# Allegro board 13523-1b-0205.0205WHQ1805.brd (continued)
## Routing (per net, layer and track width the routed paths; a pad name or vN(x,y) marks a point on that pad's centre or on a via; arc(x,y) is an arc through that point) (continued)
PCIE_SLOT0_RXN5: length 59.1
  BOTTOM w0.165: CN1.A26 54.79,55.83 54.86,55.61 55.1,55.49 55.28,55.08 55.28,52.44 55.28,52.44 55.28,52.05 55.28,51.85 55.57,51.3 56.06,50.95 56.29,50.49 56.43,49.14 56.88,47.07 56.79,46.55 54.06,31.07 38.58,8.97 38.29,7.32 38.29,6.11 38.65,5.75 GF1.A26
PCIE_SLOT0_RXN6: length 58.9
  BOTTOM w0.165: GF1.A22 34.65,5.74 34.29,6.1 34.29,8.31 34.49,9.44 49.39,30.72 52.5,48.38 52.29,50.49 52.06,50.95 51.57,51.3 51.28,51.85 51.28,52.05 51.28,52.44 51.32,54.68 51.12,55.48 50.86,55.61 50.79,55.83 CN1.A22
PCIE_SLOT0_RXN7: length 60.7
  BOTTOM w0.165: GF1.A17 29.65,5.75 29.29,6.11 29.29,8.02 29.38,8.55 29.69,8.99 31.34,10.15 45.8,30.79 47.81,42.19 47.94,42.28 48.02,42.76 47.93,42.89 48.02,43.38 48.15,43.47 48.23,43.96 48.14,44.09 48.23,44.58 48.36,44.67 48.44,45.16 48.35,45.29 48.44,45.77 48.5,46.12 48.52,46.25 48.23,48.29 48.31,50.08 48.27,50.61 47.96,50.99 47.61,51.24 47.33,51.54 47.3,52.31 47.1,52.79 46.71,53.12 45.98,53.28 45.37,54.01 45.3,54.66 45.42,55.29 45.56,55.36 45.79,55.29 CN1.A17
PCIE_SLOT0_RXP0: length 58
  BOTTOM w0.165: CN1.A47 76.51,55.29 76.74,55.36 76.88,55.29 77.01,54.61 77,52.08 76.86,51.4 76.41,51 76.08,50.58 76.04,50.06 76.04,49.56 75.93,49.45 75.94,48.95 76.05,48.84 76.06,48.35 75.95,48.23 75.95,47.74 76.07,47.63 76.07,47.13 75.96,47.02 75.97,46.52 76.08,46.41 76.09,45.6 73.79,32.52 61.55,15.05 60.01,6.3 60.01,6.11 59.65,5.75 GF1.A47
PCIE_SLOT0_RXP1: length 59
  BOTTOM w0.165: GF1.A43 55.65,5.75 56.01,6.11 56.01,6.99 56.74,11.12 72.2,33.2 74.46,46.01 74.38,46.79 74.26,46.89 74.21,47.38 74.31,47.5 74.26,48 74.14,48.1 74.09,48.59 74.19,48.71 74.14,49.2 74.02,49.3 73.97,49.8 74.07,49.92 74.02,50.41 73.84,50.76 73.35,51.11 73.03,51.72 73,51.78 73,51.89 73,52.57 73.01,54.61 72.88,55.29 72.74,55.36 72.61,55.32 72.45,55.17 CN1.A43
PCIE_SLOT0_RXP2: length 59
  BOTTOM w0.165: CN1.A39 68.51,55.29 68.74,55.36 68.88,55.29 68.88,55.29 69.01,54.85 69,52.44 69,52.05 69,51.78 69.35,51.11 69.84,50.76 70.02,50.41 70.06,49.98 70.09,49.72 70.13,49.25 70.15,49.1 70.63,47.11 70.52,46.46 70.43,45.97 70.3,45.88 70.22,45.39 70.31,45.26 70.22,44.78 70.09,44.68 70.01,44.2 70.1,44.07 70.01,43.58 69.88,43.49 69.8,43 69.89,42.87 67.77,30.88 52.31,8.8 52.01,7.11 52.01,6.11 51.65,5.75 GF1.A39
PCIE_SLOT0_RXP3: length 58.9
  BOTTOM w0.165: GF1.A35 47.65,5.75 48.01,6.11 48.01,7.77 48.09,8.25 63.12,29.71 65.66,44.1 65.57,44.23 65.65,44.72 65.78,44.81 65.87,45.3 65.78,45.43 65.87,45.91 65.99,46.01 66.08,46.49 65.99,46.62 66.08,47.11 66.21,47.2 66.29,47.69 66.02,50.4 66.02,50.41 65.84,50.76 65.35,51.11 65,51.78 65,52.05 65,52.44 65,52.45 65.04,54.68 64.88,55.29 64.74,55.36 64.51,55.29 CN1.A35
PCIE_SLOT0_RXP4: length 58.7
  BOTTOM w0.165: GF1.A29 41.65,5.75 42.01,6.11 42.01,7.55 42.36,9.52 56.81,30.16 59.52,45.51 59.43,45.64 59.51,46.13 59.64,46.22 59.73,46.71 59.64,46.83 59.72,47.32 59.85,47.41 59.94,47.9 59.85,48.03 59.94,48.52 60.06,48.61 60.15,49.1 60.02,50.41 59.84,50.76 59.35,51.11 59,51.78 59,52.05 59,52.44 59.04,54.59 58.88,55.29 58.74,55.36 58.51,55.29 CN1.A29
PCIE_SLOT0_RXP5: length 59
  BOTTOM w0.165: CN1.A25 54.51,55.29 54.74,55.36 54.88,55.29 55,55.02 55,52.44 55,52.05 55,51.78 55.35,51.11 55.84,50.76 56.02,50.41 56.15,49.09 56.59,47.06 56.51,46.6 56.43,46.11 56.3,46.02 56.21,45.54 56.3,45.41 56.22,44.92 56.09,44.83 56,44.34 56.09,44.21 56.01,43.72 55.88,43.63 55.79,43.14 55.88,43.01 53.79,31.18 38.31,9.07 38.01,7.35 38.01,6.11 37.65,5.75 GF1.A25
PCIE_SLOT0_RXP6: length 58.8
  BOTTOM w0.165: CN1.A21 50.51,55.29 50.74,55.36 50.88,55.29 51.04,54.65 51,52.46 51,52.44 51,52.05 51,51.78 51.35,51.11 51.84,50.76 51.97,50.51 52.02,50.41 52.22,48.39 52.13,47.91 52.01,47.82 51.92,47.33 52.01,47.2 51.92,46.71 51.79,46.62 51.71,46.13 51.8,46 51.71,45.51 51.58,45.42 51.5,44.94 51.59,44.81 49.12,30.83 34.22,9.55 34.01,8.34 34.01,6.12 33.65,5.76 GF1.A21
PCIE_SLOT0_RXP7: length 60.7
  BOTTOM w0.165: CN1.A16 45.51,55.83 45.44,55.61 45.17,55.47 45.02,54.67 45.1,53.89 45.82,53.02 46.58,52.86 46.87,52.62 47.02,52.25 47.06,51.43 47.42,51.03 47.77,50.78 47.99,50.5 48.03,50.08 47.95,48.27 48.24,46.25 48.16,45.82 45.53,30.9 31.14,10.35 29.49,9.19 29.12,8.66 29.01,8.05 29.01,6.11 28.65,5.75 GF1.A16
PCIE_SLOT0_TXN0: length 53.1
  TOP w0.165: GF1.B46 58.65,5.75 58.29,6.11 58.29,8 58.51,9.27 58.64,9.37 58.73,9.85 58.64,9.98 58.73,10.47 58.86,10.56 58.94,11.05 58.85,11.18 58.94,11.67 59.07,11.76 59.15,12.24 59.06,12.37 61.23,24.66 61.67,27.19 74.4,45.36 74.4,45.37 74.4,45.37 74.46,45.52 74.47,45.53 74.69,46.4 74.7,46.42 74.77,47.3 74.3,50.03 74.25,50.37 74.27,50.61 74.42,50.79 74.56,50.86 74.79,50.79 CN1.B46
PCIE_SLOT0_TXN1: length 53
  TOP w0.165: CN1.B42 70.79,50.79 70.57,50.86 70.42,50.79 70.27,50.61 70.25,50.37 70.3,50.03 70.4,49.45 70.58,48.39 70.74,47.35 70.73,47.3 70.44,46.36 69.38,43.88 69.36,43.86 57.68,27.17 54.95,11.73 55.05,11.6 54.96,11.11 54.83,11.02 54.74,10.53 54.83,10.4 54.75,9.91 54.62,9.82 54.53,9.34 54.62,9.21 54.54,8.72 54.41,8.63 54.29,7.96 54.29,6.11 54.65,5.75 GF1.B42
PCIE_SLOT0_TXN2: length 52.9
  TOP w0.165: CN1.B38 66.79,50.79 66.57,50.86 66.42,50.79 66.27,50.61 66.25,50.37 66.3,50.03 66.76,47.33 66.28,44.38 53.06,23.56 50.96,11.62 51.05,11.49 50.96,11 50.83,10.91 50.75,10.42 50.84,10.29 50.75,9.81 50.62,9.72 50.53,9.23 50.63,9.1 50.54,8.61 50.41,8.52 50.29,7.84 50.29,6.11 50.65,5.75 GF1.B38
PCIE_SLOT0_TXN3: length 53.3
  TOP w0.165: CN1.B34 62.79,50.79 62.56,50.86 62.42,50.79 62.27,50.61 62.24,50.37 62.3,50.03 62.66,47.9 62.76,47.34 62.26,44.49 62.2,44.17 62.15,43.87 61.39,39.57 48.19,20.71 46.68,12.2 46.78,12.07 46.69,11.58 46.56,11.49 46.47,11 46.56,10.87 46.48,10.39 46.35,10.29 46.26,9.81 46.35,9.68 46.27,9.19 46.14,9.1 45.99,8.26 46.29,6.56 46.29,6.11 46.65,5.75 GF1.B34
PCIE_SLOT0_TXN4: length 53.1
  TOP w0.165: CN1.B28 56.79,50.79 56.57,50.86 56.42,50.79 56.27,50.61 56.25,50.37 56.3,50.03 56.61,48.21 56.62,48.19 56.62,46.85 56.62,45.58 56.59,45.3 56.59,45.29 54.58,33.91 41.78,15.62 41.14,11.99 41.23,11.86 41.14,11.37 41.01,11.28 40.92,10.79 41.01,10.66 40.93,10.17 40.8,10.08 40.71,9.59 40.8,9.47 40.72,8.98 40.59,8.89 40.29,7.19 40.29,6.11 40.65,5.75 GF1.B28
PCIE_SLOT0_TXN5: length 53.1
  TOP w0.165: GF1.B24 36.65,5.75 36.29,6.11 36.29,8.21 36.83,11.3 49.72,29.71 52.12,43.33 52.12,43.33 52.17,43.6 52.39,45.13 52.51,45.23 52.58,45.72 52.49,45.84 52.56,46.33 52.68,46.43 52.75,46.92 52.66,47.05 52.7,47.37 52.73,47.54 52.58,48.42 52.67,48.55 52.58,49.04 52.46,49.13 52.37,49.62 52.3,50.03 52.25,50.37 52.27,50.61 52.42,50.79 52.56,50.86 52.79,50.79 CN1.B24
PCIE_SLOT0_TXN6: length 53.5
  TOP w0.165: CN1.B20 48.79,50.79 48.57,50.86 48.42,50.79 48.27,50.61 48.25,50.37 48.3,50.03 48.46,49.13 48.58,49.04 48.67,48.55 48.58,48.42 48.66,47.94 48.79,47.84 48.87,47.36 48.78,47.23 48.86,46.74 48.99,46.65 49.07,46.16 48.98,46.03 49.26,44.37 46.49,28.65 32.41,8.53 32.29,7.87 32.29,6.11 32.65,5.75 GF1.B20
PCIE_SLOT0_TXN7: length 57
  TOP w0.165: GF1.B15 27.65,5.75 27.29,6.11 27.29,7.18 27.21,7.65 27.37,8.57 31.33,14.23 37.03,18.22 45.07,29.69 46.54,38.03 47.79,44.18 47.75,44.27 46.81,46.09 45.65,48.36 44.7,48.83 44.3,49.51 44.32,50.1 44.13,50.98 43.86,51.11 43.79,51.33 CN1.B15
PCIE_SLOT0_TXP0: length 53.2
  TOP w0.165: CN1.B45 74.51,51.33 74.44,51.11 74.24,51.01 74,50.72 73.96,50.36 74.03,49.98 74.49,47.28 74.42,46.47 74.41,46.45 74.21,45.63 74.14,45.48 74.14,45.47 74.14,45.47 61.41,27.29 58.01,8.02 58.01,6.11 57.65,5.75 GF1.B45
PCIE_SLOT0_TXP1: length 53.1
  TOP w0.165: CN1.B41 70.51,51.33 70.44,51.11 70.24,51.01 70,50.72 69.96,50.36 70.03,49.98 70.31,48.34 70.45,47.37 70.18,46.45 69.13,44.02 57.41,27.28 57.18,25.95 55.5,16.46 54.01,7.98 54.01,6.11 53.65,5.75 GF1.B41
PCIE_SLOT0_TXP2: length 52.9
  TOP w0.165: CN1.B37 66.51,51.33 66.44,51.11 66.24,51.01 66,50.72 65.96,50.36 66.03,49.98 66.48,47.33 66.02,44.48 52.8,23.66 50.01,7.86 50.01,6.11 49.65,5.75 GF1.B37
PCIE_SLOT0_TXP3: length 53.3
  TOP w0.165: GF1.B33 45.65,5.75 46.01,6.11 46.01,6.53 45.71,8.26 47.92,20.82 61.13,39.68 61.87,43.92 61.93,44.21 61.98,44.53 62.48,47.34 62.39,47.86 62.03,49.98 61.96,50.36 62,50.72 62.24,51.01 62.44,51.11 62.51,51.33 CN1.B33
PCIE_SLOT0_TXP4: length 53.1
  TOP w0.165: CN1.B27 56.51,51.33 56.44,51.11 56.24,51.01 56,50.72 55.96,50.36 56.03,49.98 56.34,48.17 56.34,46.85 56.35,45.6 56.31,45.34 56.31,45.34 54.32,34.02 41.51,15.73 40.01,7.22 40.01,6.11 39.65,5.75 GF1.B27
PCIE_SLOT0_TXP5: length 53.2
  TOP w0.165: GF1.B23 35.65,5.75 36.01,6.11 36.01,8.23 36.57,11.41 49.46,29.82 51.81,43.16 51.85,43.37 51.89,43.64 52.42,47.41 52.44,47.53 52.03,49.98 51.96,50.36 52,50.72 52.24,51.01 52.44,51.11 52.51,51.33 CN1.B23
PCIE_SLOT0_TXP6: length 53.6
  TOP w0.165: GF1.B19 31.65,5.75 32.01,6.11 32.01,7.89 32.14,8.64 46.23,28.76 48.98,44.37 48.03,49.98 47.96,50.36 48,50.72 48.24,51.01 48.44,51.11 48.51,51.33 CN1.B19
PCIE_SLOT0_TXP7: length 56.9
  TOP w0.165: CN1.B14 43.51,50.79 43.74,50.86 43.88,50.79 44.04,50.07 44.03,49.78 44.02,49.43 44.46,48.69 44.5,48.62 45.44,48.15 45.67,47.71 45.62,47.56 45.85,47.12 46,47.07 46.22,46.63 46.17,46.48 46.4,46.04 46.55,45.99 46.78,45.55 46.73,45.4 46.95,44.96 47.1,44.91 47.5,44.14 46.26,38.09 44.8,29.8 36.83,18.42 31.13,14.43 27.11,8.68 26.92,7.65 27.01,7.15 27.01,6.11 26.65,5.75 GF1.B14
PCIE_SLOT1_CPRSNT1_N: length 92
  TOP w0.191: v1(62.76,10.42) 61.83,10.42 60.65,8.51 GF1.B48 ; CN2.B31 60.15,72.47 61.11,73.43 62.72,73.43 v2(62.89,73.26)
  L3 w0.216: v1(62.76,10.42) 62.76,30.65 81.54,49.43 81.54,53.97 62.89,72.62 v2(62.89,73.26)
PCIE_SLOT1_CPRSNT2_N: length 84.2
  TOP w0.191: v2(76.85,71.85) 76.85,71.77 77.15,71.47 CN2.B48 ; GF1.B81 93.65,7.86 93.68,7.92 93.68,11.19 v1(94.76,12.27)
  L3 w0.216: v2(76.85,71.85) 76.85,59.75 82.23,54.37 82.23,14.33 84.39,12.17 94.65,12.17 v1(94.76,12.27)
PCIE_SLOT1_CPRSNT3_N: length 83.8
  TOP w0.191: v2(127.04,14.86) 127.32,14.57 127.32,5.62 127.65,5.29 GF1.B115 ; CN2.B81 110.15,71.88 110.4,72.14 v2(110.42,72.14)
  BOTTOM w0.191: v2(110.42,72.14) 110.34,72.06 110.31,71.85 110.31,60.22 109.19,59.1 109.19,24.32 115.78,17.74 117.06,17.74 119.94,14.86 v2(127.04,14.86)
PCIE_SLOT1_RXN0: length 104.3
  TOP w0.165: CN2.A17 46.15,76.07 45.79,75.71 45.79,75.23 v2(46.16,74.86)
  BOTTOM w0.165: v2(46.16,74.86) 45.81,74.51 45.81,74.33 54.83,68.6 67.99,66.35 83.1,55.77 85.2,47.88 85.14,47.54 83.2,36.5 65.91,11.81 65.28,8.24 65.28,6.13 65.65,5.76 GF1.A53
PCIE_SLOT1_RXN1: length 100.7
  TOP w0.165: CN2.A22 51.15,76.07 50.79,75.71 50.79,75.23 v2(51.16,74.86)
  BOTTOM w0.165: v2(51.16,74.86) 50.83,74.4 50.87,74.16 50.88,74.08 50.9,73.97 50.95,73.62 56.33,69.85 68.52,67.7 84.3,56.66 86.73,47.51 84.74,36.16 70.67,16.08 69.29,8.24 69.29,6.05 69.65,5.69 GF1.A57
PCIE_SLOT1_RXN2: length 97.8
  TOP w0.165: CN2.A26 55.15,76.07 54.79,75.71 54.79,75.23 v2(55.16,74.86)
  BOTTOM w0.165: GF1.A61 73.65,5.73 73.3,6.08 73.3,8.24 75.44,20.33 86.11,35.57 88.32,48.11 85.55,57.58 68.8,69.31 58.52,71.12 54.95,73.62 54.9,73.92 54.88,74.08 54.87,74.16 54.83,74.39 v2(55.16,74.86)
PCIE_SLOT1_RXN3: length 94.6
  TOP w0.165: v2(59.16,74.86) 58.79,75.23 58.79,75.71 59.15,76.07 CN2.A30
  BOTTOM w0.165: v2(59.16,74.86) 58.84,74.34 58.86,74.2 58.91,73.86 59.99,73.11 61.11,72.32 68.85,70.96 86.85,58.36 89.8,48.42 87.42,34.9 80.2,24.59 77.32,8.26 77.32,6.05 77.65,5.72 GF1.A65
PCIE_SLOT1_RXN4: length 89.7
  TOP w0.165: v2(65.16,74.86) 64.79,75.23 64.79,75.71 65.15,76.07 CN2.A36
  BOTTOM w0.165: GF1.A69 81.65,5.71 81.27,6.09 81.27,8.44 81.4,9.18 84.81,28.49 84.82,28.59 88.73,34.17 91.26,48.53 88.01,59.37 68.38,73.11 65.41,73.67 64.81,74.12 64.81,74.51 v2(65.16,74.86)
PCIE_SLOT1_RXN5: length 86.7
  TOP w0.165: CN2.A40 69.15,76.07 68.79,75.71 68.79,75.23 v2(69.16,74.86)
  BOTTOM w0.165: v2(69.16,74.86) 69.12,74.46 69.61,73.93 69.68,73.88 89.27,60.16 89.3,60.07 89.32,60 92.78,48.47 90.06,33.08 88.34,30.62 85.96,17.11 86.39,14.63 85.91,11.89 86,11.76 85.92,11.27 85.79,11.18 85.7,10.69 85.79,10.56 85.71,10.08 85.58,9.99 85.49,9.5 85.58,9.37 85.49,8.88 85.37,8.79 85.27,8.24 85.27,6.14 85.65,5.76 GF1.A73
PCIE_SLOT1_RXN6: length 85.1
  TOP w0.165: CN2.A44 73.15,76.07 72.79,75.71 72.79,75.23 v2(73.16,74.86)
  BOTTOM w0.165: v2(73.16,74.86) 72.81,74.52 72.84,74.21 72.86,74.08 72.89,73.88 73,73.3 90.38,61.13 94.44,49.21 91.4,32 90.23,30.32 88.09,18.21 89.18,12.02 89.28,8.49 89.28,6.08 89.65,5.71 GF1.A77
PCIE_SLOT1_RXN7: length 83.1
  TOP w0.165: CN2.A48 77.15,76.07 76.79,75.71 76.79,75.23 v2(77.16,74.86)
  BOTTOM w0.165: GF1.A81 93.65,5.76 93.29,6.12 93.29,8.39 91.02,21.28 95.92,49.09 91.38,62.44 77.74,71.99 77.02,73.19 77.01,73.2 76.81,74.34 76.81,74.51 v2(77.16,74.86)
PCIE_SLOT1_RXN8: length 81.3
  TOP w0.165: v2(82.16,74.86) 81.79,75.23 81.79,75.71 82.15,76.07 CN2.A53
  BOTTOM w0.165: GF1.A87 99.65,5.69 99.3,6.05 99.3,8.49 99.24,8.79 98.86,9.33 96.85,10.75 96.85,10.75 93.72,28.47 97.34,49.17 92.54,63.31 81.82,74.37 81.81,74.51 v2(82.16,74.86)
PCIE_SLOT1_RXN9: length 81.5
  TOP w0.165: v2(86.16,74.86) 85.79,75.23 85.79,75.71 86.15,76.07 CN2.A57
  BOTTOM w0.165: GF1.A91 103.65,5.73 103.28,6.1 103.28,8.55 103.22,8.85 102.84,9.39 97.94,12.83 97.91,12.98 95.16,28.59 98.8,49.25 92.64,67.33 91.34,68.67 85.82,74.37 85.81,74.51 v2(86.16,74.86)
PCIE_SLOT1_RXN10: length 81.6
  TOP w0.165: v2(90.16,74.86) 89.79,75.23 89.79,75.71 90.15,76.07 CN2.A61
  BOTTOM w0.165: v2(90.16,74.86) 89.81,74.51 89.82,74.37 92.8,71.29 100.28,49.33 96.67,28.82 96.64,28.66 98.54,17.87 99.06,14.95 106.86,9.49 107.24,8.95 107.29,8.64 107.29,6.05 107.65,5.69 GF1.A95
PCIE_SLOT1_RXN11: length 82
  TOP w0.165: v2(94.16,74.86) 93.79,75.23 93.79,75.71 94.15,76.07 CN2.A65
  BOTTOM w0.165: v2(94.16,74.86) 93.75,74.38 93.71,74.15 93.61,73.34 93.6,73.26 101.79,49.22 98.15,28.57 100.21,16.92 110.82,9.48 111.2,8.94 111.25,8.64 111.25,6.13 111.65,5.73 GF1.A99
PCIE_SLOT1_RXN12: length 83.3
  TOP w0.165: v2(98.16,74.86) 97.79,75.23 97.79,75.71 98.15,76.07 CN2.A69
  BOTTOM w0.165: v2(98.16,74.86) 97.61,74.22 97.59,74.11 97.17,71.72 96.66,68.82 103.29,49.37 99.67,28.68 101.31,19.36 114.86,9.88 115.24,9.34 115.29,9.03 115.29,6.08 115.65,5.72 GF1.A103
PCIE_SLOT1_RXN13: length 84.6
  TOP w0.165: CN2.A73 102.15,76.07 101.79,75.71 101.79,75.23 v2(102.16,74.86)
  BOTTOM w0.165: v2(102.16,74.86) 101.61,74.18 101.51,73.62 101.24,72.08 101.17,71.72 99.83,64.08 104.77,49.57 101.12,28.85 101.12,28.73 102.5,20.9 118.3,9.83 118.84,9.45 119.22,8.91 119.27,8.61 119.27,6.14 119.65,5.76 GF1.A107
PCIE_SLOT1_RXN14: length 85.7
  TOP w0.165: CN2.A77 106.15,76.07 105.79,75.71 105.79,75.23 v2(106.16,74.86)
  BOTTOM w0.165: v2(106.16,74.86) 105.59,74.11 105.54,73.81 105.18,71.77 105.12,71.42 102.96,59.18 106.4,49.1 102.76,28.49 103.82,22.5 122.83,9.18 123.21,8.64 123.27,8.34 123.27,6.14 123.65,5.76 GF1.A111
PCIE_SLOT1_RXN15: length 86.4
  TOP w0.165: CN2.A81 110.15,76.07 109.79,75.71 109.79,75.23 v2(110.16,74.86)
  BOTTOM w0.165: v2(110.16,74.86) 109.62,74.25 109.56,73.95 109.48,73.48 109.14,71.54 109.11,71.37 106.12,54.39 107.87,49.26 104.21,28.52 105.05,23.76 125.66,9.33 126.29,8.22 126.29,6.03 126.65,5.67 GF1.A114
PCIE_SLOT1_RXP0: length 104.3
  TOP w0.165: CN2.A16 45.15,76.07 45.51,75.71 45.51,75.19 v2(45.18,74.85)
  BOTTOM w0.165: GF1.A52 64.65,5.73 65,6.08 65,8.26 65.64,11.92 82.93,36.61 84.82,47.35 84.92,47.87 82.86,55.6 67.88,66.09 54.72,68.34 54.57,68.43 45.53,74.18 45.53,74.51 v2(45.18,74.85)
PCIE_SLOT1_RXP1: length 100.7
  TOP w0.165: CN2.A21 50.15,76.07 50.51,75.71 50.51,75.19 v2(50.18,74.85)
  BOTTOM w0.165: GF1.A56 68.65,5.69 69.01,6.05 69.01,8.26 70.41,16.19 84.47,36.27 86.45,47.5 84.05,56.49 68.41,67.44 56.22,69.59 50.69,73.46 50.59,74.11 50.53,74.51 v2(50.18,74.85)
PCIE_SLOT1_RXP2: length 97.8
  TOP w0.165: CN2.A25 54.15,76.07 54.51,75.71 54.51,75.19 v2(54.18,74.85)
  BOTTOM w0.165: GF1.A60 72.65,5.73 73.03,6.1 73.03,8.26 75.17,20.43 85.85,35.68 88.03,48.09 85.31,57.41 68.69,69.04 58.41,70.86 54.69,73.46 54.63,73.87 54.6,74.03 54.59,74.12 54.53,74.51 v2(54.18,74.85)
PCIE_SLOT1_RXP3: length 94.6
  TOP w0.165: CN2.A29 58.15,76.07 58.51,75.71 58.51,75.19 v2(58.18,74.85)
  BOTTOM w0.165: v2(58.18,74.85) 58.56,74.3 58.59,74.12 58.66,73.7 59.83,72.88 61,72.06 68.74,70.69 86.61,58.18 89.51,48.4 87.15,35.01 79.93,24.7 77.04,8.29 77.04,6.08 76.65,5.69 GF1.A64
PCIE_SLOT1_RXP4: length 89.7
  TOP w0.165: v2(64.18,74.85) 64.51,75.19 64.51,75.71 64.15,76.07 CN2.A35
  BOTTOM w0.165: GF1.A68 80.65,5.7 80.99,6.04 80.99,8.46 81.13,9.23 84.53,28.54 84.53,28.54 84.56,28.7 88.46,34.28 90.97,48.52 87.77,59.19 68.27,72.85 65.3,73.4 64.53,73.98 64.53,74.51 v2(64.18,74.85)
PCIE_SLOT1_RXP5: length 86.7
  TOP w0.165: v2(68.18,74.85) 68.51,75.19 68.51,75.71 68.15,76.07 CN2.A39
  BOTTOM w0.165: GF1.A72 84.65,5.79 84.99,6.13 84.99,8.26 86.11,14.63 85.67,17.11 88.08,30.73 89.8,33.19 92.49,48.45 89.03,59.99 70.09,73.25 69.43,73.72 69.25,73.91 68.89,74.3 v2(68.18,74.85)
PCIE_SLOT1_RXP6: length 85.1
  TOP w0.165: v2(72.18,74.85) 72.51,75.19 72.51,75.71 72.15,76.07 CN2.A43
  BOTTOM w0.165: v2(72.18,74.85) 72.53,74.51 72.58,74.04 72.62,73.83 72.74,73.14 90.15,60.95 94.15,49.19 91.14,32.11 89.96,30.43 87.81,18.21 88.91,11.99 89,8.49 89,6.05 88.65,5.7 GF1.A76
PCIE_SLOT1_RXP7: length 83.1
  TOP w0.165: CN2.A47 76.15,76.07 76.51,75.71 76.51,75.19 v2(76.18,74.85)
  BOTTOM w0.165: v2(76.18,74.85) 76.53,74.51 76.53,74.32 76.75,73.09 77.54,71.8 91.15,62.27 95.64,49.06 90.74,21.28 93.01,8.37 93.01,6.15 92.65,5.79 GF1.A80
PCIE_SLOT1_RXP8: length 81.3
  TOP w0.165: CN2.A52 81.15,76.07 81.51,75.71 81.51,75.19 v2(81.18,74.85)
  BOTTOM w0.165: v2(81.18,74.85) 81.54,74.45 81.55,74.25 92.29,63.16 97.05,49.15 93.44,28.47 96.59,10.58 98.66,9.13 98.98,8.68 99.02,8.46 99.02,6.06 98.65,5.69 GF1.A86
PCIE_SLOT1_RXP9: length 81.5
  TOP w0.165: CN2.A56 85.15,76.07 85.51,75.71 85.51,75.19 v2(85.18,74.85)
  BOTTOM w0.165: v2(85.18,74.85) 85.53,74.51 85.53,74.49 85.54,74.35 85.55,74.25 91.14,68.47 92.4,67.18 98.51,49.23 94.87,28.59 97.68,12.67 102.64,9.19 102.96,8.74 103,8.52 103,6.1 102.65,5.76 GF1.A90
PCIE_SLOT1_RXP10: length 81.6
  TOP w0.165: CN2.A60 89.15,76.07 89.51,75.71 89.51,75.19 v2(89.18,74.85)
  BOTTOM w0.165: v2(89.18,74.85) 89.53,74.51 89.55,74.25 92.55,71.15 100,49.3 96.36,28.66 96.36,28.61 98.27,17.82 98.8,14.79 106.66,9.29 106.97,8.84 107.01,8.62 107.01,6.03 106.65,5.67 GF1.A94
PCIE_SLOT1_RXP11: length 82
  TOP w0.165: CN2.A64 93.15,76.07 93.51,75.71 93.51,75.19 v2(93.18,74.85)
  BOTTOM w0.165: v2(93.18,74.85) 93.47,74.42 93.44,74.18 93.31,74.09 93.22,73.61 93.31,73.48 93.31,73.23 101.51,49.19 97.87,28.57 99.95,16.75 110.62,9.28 110.93,8.83 110.97,8.61 110.97,6.13 110.65,5.81 GF1.A98
PCIE_SLOT1_RXP12: length 83.3
  TOP w0.165: CN2.A68 97.15,76.07 97.51,75.71 97.51,75.19 v2(97.18,74.85)
  BOTTOM w0.165: GF1.A102 114.65,5.72 115.01,6.08 115.01,9.01 114.97,9.23 114.66,9.68 101.06,19.2 99.39,28.68 103,49.35 96.37,68.8 96.75,70.92 96.9,71.77 96.81,71.89 96.89,72.38 97.02,72.47 97.11,72.96 97.02,73.09 97.1,73.58 97.23,73.67 97.34,74.28 v2(97.18,74.85)
PCIE_SLOT1_RXP13: length 84.5
  TOP w0.165: v2(101.18,74.85) 101.51,75.19 101.51,75.71 101.15,76.07 CN2.A72
  BOTTOM w0.165: v2(101.18,74.85) 101.34,74.28 101.25,73.76 101.12,73.67 101.03,73.19 101.12,73.06 101.04,72.57 100.91,72.48 100.82,71.99 100.91,71.86 100.9,71.77 100.78,71.08 99.54,64.06 104.48,49.55 100.84,28.9 100.84,28.88 100.84,28.71 102.24,20.73 118.14,9.6 118.64,9.25 118.95,8.8 118.99,8.58 118.99,6.15 118.65,5.81 GF1.A106
PCIE_SLOT1_RXP14: length 85.7
  TOP w0.165: CN2.A76 105.15,76.07 105.51,75.71 105.51,75.19 v2(105.18,74.85)
  BOTTOM w0.165: v2(105.18,74.85) 105.33,74.22 105.27,73.86 105.18,73.37 105.05,73.28 104.96,72.79 105.05,72.66 104.97,72.18 104.84,72.09 104.75,71.6 104.84,71.47 104.79,71.15 102.67,59.15 106.11,49.08 102.48,28.49 103.56,22.34 122.63,8.98 122.95,8.53 122.99,8.31 122.99,6.08 122.65,5.74 GF1.A110
PCIE_SLOT1_RXP15: length 86.4
  TOP w0.165: v2(109.18,74.85) 109.51,75.19 109.51,75.71 109.15,76.07 CN2.A80
  BOTTOM w0.165: GF1.A113 125.65,5.67 126.01,6.03 126.01,8.15 125.45,9.13 104.8,23.6 103.93,28.52 107.58,49.24 105.96,53.98 105.85,54.3 105.83,54.37 105.84,54.44 108.7,70.67 108.84,71.42 108.75,71.55 108.83,72.04 108.96,72.13 109.05,72.62 108.96,72.75 109.04,73.23 109.17,73.32 109.26,73.81 109.32,74.16 v2(109.18,74.85)
PCIE_SLOT1_TXN0: length 100.9
  TOP w0.165: CN2.B15 43.87,68.66 44.23,68.3 45.31,67.97 45.32,67.97 45.63,67.84 66.92,58.82 77.63,57.8 82.6,54.98 84.99,46.75 83.18,36.48 63.61,8.53 63.29,6.71 63.29,6.11 63.65,5.75 GF1.B51
PCIE_SLOT1_TXN1: length 98
  TOP w0.165: GF1.B55 67.65,5.75 67.29,6.11 67.29,7.48 68.18,12.52 84.72,36.14 86.77,47.8 84.75,55.37 78.13,59.13 67.24,60.16 49.32,67.75 48.79,68.35 48.79,68.73 49.15,69.09 CN2.B20
PCIE_SLOT1_TXN2: length 95.6
  TOP w0.165: CN2.B24 53.15,68.97 52.81,68.63 52.78,68.35 52.84,68.1 52.86,68.01 52.92,67.73 52.93,67.71 67.62,61.49 78.57,60.45 85.91,56.29 88.31,48.08 87.02,40.8 86.1,35.55 71.61,14.86 71.29,13.04 71.29,6.11 71.65,5.75 GF1.B59
PCIE_SLOT1_TXN3: length 92.4
  TOP w0.165: CN2.B28 57.15,68.97 56.81,68.63 56.83,68.59 57.35,67.39 57.45,67.35 57.45,67.35 68.14,62.81 79.02,61.78 87.18,57.15 87.22,57.01 89.78,48.4 87.4,34.88 76.69,19.59 75.29,11.64 75.29,6.11 75.65,5.75 GF1.B63
PCIE_SLOT1_TXN4: length 88.2
  TOP w0.165: CN2.B34 63.15,68.97 62.81,68.63 62.79,68.46 63,67.23 70.78,63.93 79.49,63.11 88.38,58.06 91.25,48.51 88.71,34.15 79.96,21.65 79.29,17.85 79.29,6.11 79.65,5.75 GF1.B67
PCIE_SLOT1_TXN5: length 85.6
  TOP w0.165: CN2.B38 67.15,68.97 66.81,68.63 66.81,68.17 67.75,66.96 71.92,65.2 79.89,64.44 89.68,58.89 92.78,48.55 90.05,33.06 86.93,28.6 83.11,23.16 81.79,15.66 83.29,7.17 83.29,6.11 83.65,5.75 GF1.B71
PCIE_SLOT1_TXN6: length 81.8
  TOP w0.165: GF1.B75 87.65,5.75 87.29,6.11 87.29,13.73 90.21,30.3 91.39,31.98 94.42,49.19 90.85,59.69 90.78,59.91 80.46,65.76 72.66,66.5 71.1,67.72 70.8,68.54 CN2.B42
PCIE_SLOT1_TXN7: length 78.9
  TOP w0.165: CN2.B46 74.86,68.65 75.44,67.6 80.93,67.08 91.9,60.86 95.91,49.06 91.29,22.87 91.29,6.11 91.65,5.75 GF1.B79
PCIE_SLOT1_TXN8: length 75.8
  TOP w0.165: CN2.B51 80.04,68.74 80.11,68.68 80.12,68.67 80.43,68.57 81.33,68.43 93.03,61.79 97.33,49.15 93.71,28.45 93.72,28.4 96.66,11.71 96.79,11.62 96.87,11.14 96.78,11.01 96.87,10.52 97,10.43 97.08,9.94 96.99,9.81 97.08,9.32 97.21,9.23 97.29,8.74 97.2,8.61 97.29,8.13 97.29,6.11 97.65,5.75 GF1.B85
PCIE_SLOT1_TXN9: length 74.8
  TOP w0.165: CN2.B55 84.04,68.74 84.09,68.53 84.97,67.98 94.18,62.75 98.79,49.23 98.68,48.62 98.68,48.62 95.14,28.57 97.83,13.31 98.89,11.8 99.05,11.77 99.33,11.37 99.3,11.21 99.59,10.81 99.74,10.78 100.03,10.37 100,10.22 100.28,9.81 100.44,9.78 100.72,9.38 100.7,9.22 100.98,8.82 101.29,7.06 101.29,6.11 101.65,5.75 GF1.B89
PCIE_SLOT1_TXN10: length 74.1
  TOP w0.165: GF1.B93 105.65,5.75 105.29,6.11 105.29,7.27 104.84,9.83 98.29,19.18 96.62,28.64 100.27,49.3 95.34,63.76 87.81,68.34 87.81,68.78 88.15,69.11 CN2.B59
PCIE_SLOT1_TXN11: length 73.1
  TOP w0.165: GF1.B97 109.65,5.75 109.29,6.11 109.29,7.66 109.12,8.61 99.14,22.87 98.14,28.55 101.78,49.19 96.55,64.53 91.81,68.43 91.81,68.63 92.15,68.97 CN2.B63
PCIE_SLOT1_TXN12: length 72.6
  TOP w0.165: GF1.B101 113.65,5.75 113.29,6.11 113.29,8.05 113.03,9.51 99.63,28.65 103.28,49.35 97.5,66.31 95.79,68.42 95.79,68.61 96.15,68.97 CN2.B67
PCIE_SLOT1_TXN13: length 72.7
  TOP w0.165: GF1.B105 117.65,5.75 117.29,6.11 117.29,7.78 117.03,9.23 101.6,31.27 101.92,33.11 104.8,49.42 99.15,66 99.79,68 99.79,68.71 100.15,69.07 CN2.B71
PCIE_SLOT1_TXN14: length 73.2
  TOP w0.165: CN2.B75 104.15,69.11 103.79,68.75 103.79,68.07 101.94,62.13 106.56,48.54 103.93,33.63 103.93,33.63 121.09,9.12 121.29,8 121.29,6.11 121.65,5.75 GF1.B109
PCIE_SLOT1_TXN15: length 75.1
  TOP w0.165: GF1.B113 125.65,5.75 125.29,6.11 125.29,8.39 125.21,8.47 121.79,12.08 121.35,12.71 113.56,23.83 105.78,34.95 108.14,48.38 103.52,62 106.85,67.24 107.79,68.55 107.79,68.79 108.15,69.15 CN2.B79
PCIE_SLOT1_TXP0: length 101
  TOP w0.165: GF1.B50 62.65,5.75 63.01,6.11 63.01,6.74 63.35,8.64 82.92,36.59 84.7,46.73 82.37,54.79 77.55,57.53 66.85,58.54 45.23,67.7 44.09,68.05 43.55,68.59 CN2.B14
PCIE_SLOT1_TXP1: length 98
  TOP w0.165: CN2.B19 48.15,69.18 48.51,68.82 48.51,68.24 49.15,67.52 67.17,59.88 78.04,58.85 84.51,55.18 86.49,47.78 84.46,36.25 67.91,12.63 67.01,7.51 67.01,6.11 66.65,5.75 GF1.B54
PCIE_SLOT1_TXP2: length 95.6
  TOP w0.165: CN2.B23 52.15,69.04 52.53,68.66 52.52,68.49 52.5,68.33 52.56,68.07 52.59,67.95 52.69,67.51 67.55,61.22 78.48,60.18 85.67,56.1 88.02,48.07 85.83,35.66 71.35,14.97 71.01,13.06 71.01,6.11 70.65,5.75 GF1.B58
PCIE_SLOT1_TXP3: length 92.5
  TOP w0.165: CN2.B27 56.15,69.04 56.48,68.71 56.48,68.69 57.13,67.18 68.08,62.54 78.93,61.51 86.95,56.96 89.5,48.38 87.14,34.99 76.43,19.69 75.01,11.67 75.01,6.11 74.65,5.75 GF1.B62
PCIE_SLOT1_TXP4: length 88.2
  TOP w0.165: GF1.B66 78.65,5.75 79.01,6.11 79.01,17.87 79.69,21.76 88.45,34.26 90.96,48.5 88.15,57.87 79.4,62.84 70.71,63.66 62.74,67.04 62.51,68.45 62.52,68.49 62.53,68.66 62.15,69.04 CN2.B33
PCIE_SLOT1_TXP5: length 85.6
  TOP w0.165: GF1.B70 82.65,5.75 83.01,6.11 83.01,7.14 81.51,15.66 82.85,23.27 86.7,28.76 89.78,33.17 92.49,48.53 89.44,58.7 79.81,64.17 71.85,64.92 67.58,66.73 66.53,68.08 66.53,68.66 66.15,69.04 CN2.B37
PCIE_SLOT1_TXP6: length 81.8
  TOP w0.165: CN2.B41 70.42,68.77 70.54,68.43 70.82,67.66 70.86,67.55 72.55,66.23 80.37,65.49 90.55,59.71 94.13,49.16 91.12,32.09 89.95,30.41 87.01,13.75 87.01,6.11 86.65,5.75 GF1.B74
PCIE_SLOT1_TXP7: length 79
  TOP w0.165: GF1.B78 90.65,5.75 91.01,6.11 91.01,22.9 95.62,49.04 91.67,60.67 80.85,66.81 75.27,67.34 74.61,68.51 74.53,68.66 CN2.B45
PCIE_SLOT1_TXP8: length 75.8
  TOP w0.165: CN2.B50 79.37,68.78 79.51,68.57 79.72,68.45 79.96,68.37 80.05,68.35 80.82,68.23 81.23,68.16 81.66,67.92 92.8,61.6 97.04,49.13 93.42,28.45 97.01,8.1 97.01,6.11 96.65,5.75 GF1.B84
PCIE_SLOT1_TXP9: length 74.8
  TOP w0.165: CN2.B54 83.35,68.69 83.93,68.3 84.83,67.73 93.95,62.56 98.5,49.21 98.44,48.9 94.86,28.57 97.57,13.2 100.72,8.71 101.01,7.03 101.01,6.11 100.65,5.75 GF1.B88
PCIE_SLOT1_TXP10: length 74.1
  TOP w0.165: CN2.B58 87.15,69.11 87.54,68.73 87.54,68.18 95.11,63.58 99.98,49.28 96.34,28.64 98.03,19.07 104.57,9.72 105.01,7.25 105.01,6.11 104.65,5.75 GF1.B92
PCIE_SLOT1_TXP11: length 73.2
  TOP w0.165: CN2.B62 91.15,69.04 91.53,68.66 91.53,68.3 96.31,64.36 101.49,49.17 97.85,28.55 98.88,22.76 108.86,8.5 109.01,7.63 109.01,6.11 108.65,5.75 GF1.B96
PCIE_SLOT1_TXP12: length 72.6
  TOP w0.165: GF1.B100 112.65,5.75 113.01,6.11 113.01,8.02 112.77,9.4 99.33,28.59 102.99,49.33 97.25,66.17 95.51,68.32 95.51,68.57 95.15,68.93 CN2.B66
PCIE_SLOT1_TXP13: length 72.7
  TOP w0.165: CN2.B70 99.15,69.03 99.51,68.67 99.51,68.05 98.86,65.99 104.51,49.4 101.65,33.16 101.31,31.21 116.77,9.13 117.01,7.75 117.01,6.11 116.65,5.75 GF1.B104
PCIE_SLOT1_TXP14: length 73.2
  TOP w0.165: CN2.B74 103.15,69.09 103.51,68.73 103.51,68.12 101.64,62.12 101.73,61.85 101.73,61.85 106.28,48.52 103.64,33.56 120.83,9.01 121.01,7.98 121.01,6.11 120.65,5.75 GF1.B108
PCIE_SLOT1_TXP15: length 75.2
  TOP w0.165: GF1.B112 124.65,5.75 125.01,6.11 125.01,8.27 121.59,11.88 121.58,11.9 121.12,12.55 105.48,34.88 107.86,48.36 103.21,62.04 106.61,67.39 106.62,67.39 107.51,68.64 107.51,68.78 107.15,69.14 CN2.B78
PCIE_SMCLK: length 74.3
  TOP w0.191: RE10.2 39.71,61.22 40.09,60.84 40.09,60.26 v2(39.73,59.9) ; GF1.B5 15.65,5.72 16,6.07 16,18.17 23.95,26.12 23.95,42.34 v1(23.51,42.79) 23.89,43.17 23.89,43.59 RE1.2
  BOTTOM w0.191: v1(23.51,42.79) 24.01,43.29 24.01,44.5 26.6,47.1 31.75,47.1 34.01,49.36 34.01,50.75 35.03,51.78 35.03,55.28 36.04,56.29 36.04,57.34 36.65,57.94 38.77,57.94 40.08,59.25 40.08,59.56 39.73,59.9 v2(39.73,59.9)
PCIE_SMDAT: length 74.2
  TOP w0.191: RE7.2 24.27,43.59 24.27,43.11 v1(24.62,42.76) 24.26,42.39 24.26,25.99 16.31,18.04 16.31,6.07 16.65,5.73 GF1.B6 ; v2(40.73,59.85) 40.39,60.18 40.39,60.88 40.75,61.24 RE9.2
  BOTTOM w0.191: v1(24.62,42.76) 24.31,43.07 24.31,44.38 26.73,46.79 31.87,46.79 34.31,49.23 34.31,50.63 35.34,51.65 35.34,55.15 36.35,56.16 36.35,57.22 36.77,57.64 38.9,57.64 40.38,59.12 40.38,59.5 v2(40.73,59.85)
PCIE_WAKE_N: length 86
  TOP w0.191: GF1.B11 21.65,5.34 21.32,5.67 21.32,8.5 v2(26.11,13.29) ; CN2.B11 38.15,72.12 v2(38.15,72.13)
  L3 w0.216: v2(26.11,13.29) 26.11,16.13 39.78,29.8 39.78,51.09 38.8,52.06 CN1.B11
  BOTTOM w0.191: v2(38.15,72.13) 38.15,71.67 42.92,66.89 42.92,59.4 40.39,56.87 40.39,55.16 41.38,54.17 41.38,52.65 40.46,51.73 38.48,51.73 CN1.B11
PERST_LAT_N: length 10.4
  TOP w0.191: R4.1 R3.2 16.69,45.83 17.28,46.42 21.4,46.42 21.67,46.15 U8.1
PERST_N: length 63.6
  TOP w0.191: U8.4 R6.1 18.41,43.01 18.15,42.75 18.15,40.18 v2(18.28,40.05) ; CN2.A11 38.15,75.57 v2(38.35,75.37)
  BOTTOM w0.191: v2(18.28,40.05) 21.36,40.05 21.43,40.11 22.03,40.11 22.1,40.05 34.43,40.05 36.51,42.13 36.51,49.63 36.39,49.75 36.39,50.37 36.51,50.49 36.51,51.02 37.24,51.75 37.24,53.65 CN1.A11 38.15,55.33 41.5,58.68 41.5,67.61 37.62,71.49 37.62,74.64 v2(38.35,75.37)
RESET_IN: length 4.7
  TOP w0.191: U1.3 13.93,43.74 14.4,44.21 C19.1 R2.1 14.74,46.6 R1.2
RESET_O: length 2.9
  TOP w0.191: U1.2 14.52,41.53 14.52,42.96 14.85,43.29 R3.1
S0_PCIE_SMCLK: length 14.2
  TOP w0.191: RE1.1 23.94,45.19 23.94,45.9 25,46.96 30.57,46.96 31.88,48.25 31.88,49.52 31.97,49.98 32.02,50.3 32.08,50.64 32.11,50.78 32.44,51.11 32.44,51.48 CN1.B5
S0_PCIE_SMDAT: length 13.9
  TOP w0.191: CN1.B6 33.15,50.18 32.85,50.79 32.58,50.79 32.38,50.59 32.32,50.25 32.27,49.93 32.19,49.49 32.19,48.13 30.7,46.65 25.13,46.65 24.24,45.77 24.24,45.16 RE7.1
S0_SMB_ALERT_B12_N: length 7.7
  TOP w0.191: RE4.1 44.19,43.93 43.63,44.49 43.63,46.67 41.15,49.15 CN1.B12
S0_SMB_CLK_A32: length 8.5
  TOP w0.191: CN1.A32 61.5,55.87 61.41,55.61 61.24,55.53 60.86,55.53 60.27,56.11 60.27,57.87 61.07,58.66 61.07,59.45 60.75,59.77 59.5,59.77 59.07,60.19 RE2.2
S0_SMB_DAT_A33: length 8.6
  TOP w0.191: CN1.A33 61.8,55.25 61.55,55.34 61.42,55.27 61.37,55.22 60.73,55.22 59.97,55.99 59.97,57.99 60.76,58.79 60.76,59.33 60.63,59.46 59.46,59.46 RE3.2
S1_PCIE_SMCLK: length 16.1
  TOP w0.191: v2(39.82,63.34) 40.06,63.1 40.06,62.68 RE10.1 ; CN2.B5 v2(32.15,71.96)
  BOTTOM w0.191: v2(32.15,71.96) 32.51,71.59 32.51,70.81 33.39,69.93 34.77,69.93 40.09,64.61 40.09,63.58 39.86,63.34 v2(39.82,63.34)
S1_PCIE_SMDAT: length 16.3
  TOP w0.191: CN2.B6 v2(33.15,71.98) ; v2(40.73,63.32) 40.58,63.32 40.36,63.1 40.36,62.72 RE9.1
  BOTTOM w0.191: v2(40.73,63.32) 40.39,63.65 40.39,64.74 34.9,70.24 33.51,70.24 32.82,70.94 32.82,71.65 v2(33.15,71.98)
S1_SMB_ALERT_B12_N: length 34.9
  TOP w0.191: v2(40.71,71.87) 41.15,71.44 CN2.B12 ; RE8.1 44.13,44.69 44.13,47.45 v2(43.86,47.71)
  L3 w0.216: v2(40.71,71.87) 40.71,71.47 46.31,65.87 46.31,55.48 46.92,54.88 46.92,51.74 46.25,51.07 46.25,50.07 45.47,49.29 45.44,49.29 v2(43.86,47.71)
S1_SMB_CLK_A32: length 23.1
  TOP w0.191: RE5.2 54.9,59.72 54.2,59.72 v2(53.8,59.94) ; CN2.A32 61.15,76.07 61.51,75.71 61.51,75.19 v2(61.18,74.85)
  L3 w0.216: v2(61.18,74.85) 61.48,74.56 61.48,74.5 61.48,74.21 60.11,72.84 60.11,65.51 54.54,59.94 v2(53.8,59.94)
S1_SMB_DAT_A33: length 24
  TOP w0.191: CN2.A33 62.15,76.07 61.82,75.73 61.82,75.2 v2(62.16,74.86) ; RE6.2 54.85,59.4 54.27,59.4 v2(53.8,59.01)
  L3 w0.216: v2(62.16,74.86) 61.81,74.51 61.81,74.08 60.44,72.7 60.44,65.37 54.4,59.34 54.12,59.34 v2(53.8,59.01)
SLOT0_CONFIG: length 106.3
  TOP w0.191: v2(118.61,59.85) 118.61,62.75 CFGCN1.1
  L3 w0.216: v2(62.21,9.41) 94.6,9.41 104.68,19.49 104.68,28.29 113.35,36.96 117.06,36.96 120.98,40.89 120.98,57.76 118.9,59.85 v2(118.61,59.85)
  BOTTOM w0.191: GF1.A50 62.65,6.34 62.76,6.44 62.76,9.01 v2(62.21,9.41)
SLOT0_ID_0: length 7.2
  TOP w0.191: R7.1 52.23,58.88 50.13,56.77 50.13,56.01 48.68,54.56 CN1.A19
SLOT0_ID_1: length 4.1
  TOP w0.191: R8.2 59.15,46.95 CN1.B30
SLOT1_CONFIG: length 72.8
  TOP w0.191: CFGCN1.3 121.22,60.24 v2(121.53,59.93)
  L3 w0.216: v2(121.53,59.93) 121.53,40.7 117.27,36.44 113.57,36.44 105.21,28.09 105.21,18.91 v1(95.1,8.8)
  BOTTOM w0.191: GF1.A83 95.65,6.42 95.39,6.69 95.39,6.94 95.1,7.23 v1(95.1,8.8)
SLOT1_ID_0: length 16.3
  TOP w0.191: R9.2 v2(52.17,63.54) ; v2(48.15,74.97) 48.15,74.97 CN2.A19
  L3 w0.216: v2(48.15,74.97) 48.71,74.4 48.71,68.74 52.17,65.28 v2(52.17,63.54)
SLOT1_ID_1: length 15.8
  TOP w0.191: v2(54.68,61.81) 53.76,62.73 R10.2 ; v2(59.22,71.93) 59.15,71.86 CN2.B30
  L3 w0.216: v2(59.22,71.93) 58.83,71.54 58.83,65.95 v2(54.68,61.81)

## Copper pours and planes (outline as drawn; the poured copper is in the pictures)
GND on TOP: 23.35,71.04 22.94,71.44 20.53,71.44 19.96,72.02 19.96,73.61 20.39,74.03 22.64,74.03 23.15,74.54 23.15,76.02 23.32,76.18 26.86,76.18 27.03,76.01 27.03,71.2 26.87,71.04 ; 6 cut-outs
GND on TOP: 1.26,24.94 0.78,25.41 0.78,76.85 0.79,76.86 0.79,77.43 1.07,77.71 10.17,77.71 11.05,76.84 11.05,58.27 4.9,52.12 4.9,37.78 11.31,31.36 11.31,25.77 10.71,25.16 9.52,25.16 8.33,26.35 8.33,27.86 6.94,29.25 5.03,29.25 3.71,27.93 3.71,26.08 2.56,24.94
GND on TOP: 47.31,58.19 46.6,58.9 46.6,63.82 45.05,65.37 42.75,65.37 42.53,65.59 42.53,67.89 42.6,67.96 43.12,67.96 43.89,67.19 44.82,66.27 46.81,66.27 47.96,65.11 47.97,65.11 48.27,64.81 50.02,64.81 50.81,64.02 50.81,58.5 50.5,58.19 ; 2 cut-outs
GND on TOP: 111.36,38.96 111.45,39.05 119,39.05 120.19,40.24 120.19,58.47 119.24,59.41 111.81,59.41 111.36,59.87 111.36,73.75 111.38,73.77 110.97,74.18 110.97,75.82 110.77,76.02 110.77,77.55 110.95,77.72 138.33,77.72 138.54,77.51 138.54,25.01 138.33,24.81 136.52,24.81 136.38,24.95 136.25,24.95 135.61,25.59 135.61,27.92 134.29,29.24 132.31,29.24 131.02,27.95 131.02,25.92 130.11,25.01 128.4,25.01 127.4,24.01 127.4,18.38 126.56,17.54 124.38,17.54 111.36,30.56
GND on TOP: 32.73,59.41 32.05,60.09 32.05,65.28 32.71,65.95 36.08,65.95 37.12,64.91 37.12,60.82 35.7,59.41
GND on TOP: 15.4,60.05 14.91,60.54 14.91,65.12 15.26,65.47 19.68,65.47 20.02,65.13 20.02,60.56 19.51,60.05
GND on TOP: 26.62,39.68 26.1,40.2 26.1,45.09 27.13,46.12 27.15,46.1 31.14,46.1 31.33,45.91 31.33,40.6 30.41,39.68
GND on BOTTOM: 137.36,77.4 137.86,76.9 137.86,25.82 137.49,25.45 136.52,25.45 135.64,26.32 135.64,27.99 134.24,29.39 132.21,29.39 130.79,27.97 130.79,25.39 130.27,24.87 128.26,24.87 127.4,24.01 127.4,17.14 126.06,15.8 119.79,15.8 109.76,25.83 109.76,34.97 111.26,36.47 111.26,38.85 111.46,39.05 119.03,39.05 120.19,40.21 120.19,58.47 119.34,59.32 111.69,59.32 111.36,59.64 111.36,73.75 110.94,74.18 110.94,74.95 113.38,77.4
GND on BOTTOM: 0.78,68.58 0.78,76.85 0.79,76.86 0.79,77.43 1.07,77.71 10.83,77.71 11.28,77.26 11.28,25.28 10.99,25 9.24,25 8.52,25.72 8.52,28.05 7.32,29.25 4.42,29.25 3.51,28.33 3.51,26.08 2.64,25.21 1.11,25.21 0.83,25.49 0.83,68.54
GND on L2GND: outline of 321 points within 0.76,2.54 138.54,77.74 ; 32 cut-outs
GND on L3: 0.77,25.02 0.98,24.8 2.63,24.8 3.65,25.83 3.65,28 4.97,29.32 6.89,29.32 8.4,27.81 8.4,26.03 9.61,24.82 11.26,24.82 11.46,25.02 11.46,77.19 10.93,77.73 1,77.73 0.77,77.5
GND on L3: 30.75,11.04 30.75,14.85 30.75,18.85 46.58,34.68 46.58,66.88 40.49,72.96 40.49,74.5 40.28,74.71 40.28,77.47 40.54,77.73 138.26,77.73 138.53,77.46 138.53,25.01 138.35,24.83 136.48,24.83 135.68,25.63 135.68,28.15 134.56,29.27 132.03,29.27 130.86,28.11 130.86,27.14 127.54,23.82 127.54,23.39 127.54,23.39 127.54,2.74 127.37,2.58 25.9,2.58 25.18,3.3 25.18,9.36 26.6,10.79 30.5,10.79
GND on L4VCC: 11.76,2.58 11.76,22.96 11.25,24.21 10,24.72 8.94,24.72 8.82,24.75 8.74,24.84 8.29,25.61 8.27,25.67 8.26,25.73 8.26,26.96 6,29.22 3.74,26.96 3.74,25.73 3.73,25.67 3.71,25.61 3.26,24.84 3.18,24.75 3.06,24.72 1,24.72 0.83,24.79 0.76,24.96 0.76,77.5 0.83,77.67 1,77.74 138.3,77.74 138.47,77.67 138.54,77.5 138.54,24.96 138.47,24.79 138.3,24.72 136.57,24.72 136.51,24.73 136.45,24.75 135.68,25.2 135.59,25.28 135.56,25.4 135.56,26.96 133.3,29.22 131.04,26.96 131.04,25.4 131.01,25.28 130.92,25.2 130.15,24.75 130.09,24.73 130.03,24.72 129.3,24.72 128.05,24.21 127.54,22.96 127.54,2.54 24.86,2.54 24.86,7.45 23.15,9.16 21.44,7.45 21.44,2.54 11.8,2.54 ; 1 cut-out
GND on L5GND: outline of 92 points within 0.76,2.54 138.54,77.74
P3V3 on TOP: 18.47,3.41 18.31,3.56 18.31,6.66 16.97,8.01 16.97,11.54 17.55,12.12 17.55,17.51 31.93,31.89 31.93,42.32 31.94,42.34 31.94,46.5 32.44,47 37.41,47 38,46.41 38,41.77 38.82,40.95 38.86,30.36 18.26,9.76 18.26,8.54 19,7.81 19,3.54 18.87,3.41 ; 5 cut-outs
P3V3 on TOP: 42.71,58.08 41.51,59.28 41.51,64.41 41.51,64.41 41.51,64.87 41.04,65.34 41.04,67.92 41.22,68.1 41.51,68.1 41.53,68.12 42.2,68.12 42.26,68.05 42.26,65.29 42.61,64.94 44.96,64.94 45.78,64.12 45.78,58.8 45.06,58.08 ; 3 cut-outs
P3V3 on TOP: 35.9,77.66 37.3,77.66 37.52,77.45 37.52,73.01 35.56,71.05 35.56,69.77 35.44,69.65 34.94,69.65 34.75,69.84 34.75,75.18 35.78,76.22 35.78,77.54
P3V3 on BOTTOM: 20.02,1.4 19.43,1.4 19.3,1.53 19.3,10.22 19.02,10.5 17.78,10.5 17.78,14.09 18.24,14.56 20.68,14.56 21.23,14 21.23,5.85 20.98,5.6 20.98,1.53 20.85,1.4 20.29,1.4 20.29,5.62 20.02,5.62
P3V3 on L3: 32.59,77.15 31.95,76.51 31.95,34.07 17.55,19.59 17.55,10.63 17.68,10.5 19.08,10.5 38.87,30.32 38.81,50.79 38.22,51.37 38.23,55.23 40.9,57.88 44.88,57.88 45.46,58.46 45.46,64.77 43.17,67.06 41.51,67.06 38.71,71.16 38.71,76.67 38.23,77.15
P3V3_AUX on TOP: 20.45,3.06 20.29,3.21 20.29,10.6 40.61,30.92 40.61,44.51 33.05,52.07 33.05,57.58 33.49,58.02 34.57,58.02 34.59,58 35.51,58 37.55,60.04 37.55,64.16 37.51,64.2 37.51,66.6 36.91,67.21 36.91,68.74 36.85,68.8 36.85,71.35 36.95,71.46 37.35,71.46 37.48,71.33 37.48,68.46 39.14,66.81 39.14,64.94 39.11,64.91 39.11,59.29 39.11,59.28 39.11,56.01 38.13,55.02 38.13,51.11 38.81,50.43 38.81,49.28 42.57,45.52 42.57,31.02 21.01,9.46 21.01,3.21 20.85,3.06 ; 2 cut-outs
P12V on TOP: 109.36,39.45 109.31,58.32 109.57,58.57 119.08,58.57 119.45,58.21 119.46,40.23 118.68,39.45
P12V on TOP: 11.63,1.4 11.4,1.63 11.4,6.04 11.84,6.47 11.84,32.35 5.51,38.67 5.51,51.26 11.84,57.59 11.84,76.44 12.52,77.12 27.35,77.12 27.55,76.92 27.55,75.03 27.94,74.64 28.59,74.64 28.83,74.88 28.83,77.66 28.87,77.7 30.4,77.7 30.47,77.63 30.47,75.57 31.04,75.01 31.04,72.77 30.33,72.07 30.33,68.77 31.06,68.04 31.06,49.92 28.91,47.76 17.42,47.76 17.39,47.73 17.36,47.75 15.89,47.75 15.39,48.25 12.42,48.25 11.36,47.19 11.36,40.33 17.04,34.65 17.04,24.6 15.29,22.84 15.29,9.05 14.68,8.44 14.68,7.15 14,6.46 14,1.51 13.89,1.4 13.28,1.4 13.28,5.62 13,5.62 13,1.4 12.27,1.4 12.27,5.57 11.99,5.57 11.99,1.4 ; 22 cut-outs
P12V on BOTTOM: 110.12,39.47 110.12,58.56 118.92,58.56 119.43,58.05 119.43,40.27 118.63,39.47
P12V on BOTTOM: 12.98,1.4 12.4,1.4 12.29,1.51 12.29,10.58 11.84,10.57 11.84,76.44 12.52,77.12 30.2,77.12 31.06,76.26 31.06,49.89 28.93,47.76 25.25,47.76 17.73,40.24 17.73,39.41 18.69,38.45 30.7,38.45 31.2,37.96 31.2,36.76 28.24,33.79 24.75,33.79 16.63,25.68 16.63,18.62 15.29,17.28 15.29,13.24 14.99,12.94 14.99,8.7 14.68,8.44 14.68,7.15 14,6.46 13.97,1.43 13.94,1.4 13.31,1.4 13.31,5.6 12.98,5.6
P12V on L3: 11.85,43.83 11.84,76.44 12.52,77.12 30.1,77.12 31.04,76.18 31.04,66.4 31.06,66.38 31.06,49.92 31.05,49.9 31.05,34.59 16.53,20.07 16.53,10.29 14.68,8.44 14.68,7.15 14.2,6.67 11.94,6.67 11.83,6.77 11.83,43.82
P12V on L4VCC: 34.38,37.78 115.54,37.78 119.66,41.89 119.66,60.05 111.83,67.88 31.15,67.88 30.38,68.66 30.38,72.57 31.09,73.28 31.09,76.15 30.1,77.14 12.55,77.14 11.81,76.39 11.81,24.25 11.82,24.24 11.82,6.32 12.32,5.81 12.34,5.79 14.23,5.79 14.72,6.28 14.72,8.37 15.45,9.11 15.45,18.83 28.45,31.83 28.45,31.84 ; 1 cut-out

Small or netless copper shapes (teardrops, artwork), in the pictures only: 2 on TOP, 2 on BOTTOM

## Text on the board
Ref Des/Silkscreen Top: 13523-1B | 48.B0F03.01B | SV7220G2 PCIE RISER | MADE IN TAIWAN
User.31: This gerber is just for you reference to find the differential traces in layer BOTTOM
User.32: This gerber is just for you reference to find the differential traces in layer TOP
User.34: Board Accuracy Check,Nov 21 13:31:18 2013,Passed | Dummy-Static-No Shape On Layer Check,Nov 21 13:31:18 2013,Passed | Split Plane Check,Nov 21 13:31:18 2013,Passed
User.35: This gerber is just for you reference to find the differential traces in layer L3
User.38: TMASK
User.39: BMASK
User.40: TSMD
User.41: BSMD
User.42: TSILK
User.43: BSILK
User.44: DRILL
User.45: Note:Refer to DRILL layer for ELLIPSE drill direction | FIGURE | SIZE | 12.0 | 16.0 | 20.0 | 28.0 | 71.0 | 223.0 | ELLIPSE | 48.0 | 86.0 | 93.0 | 119.0 | DRILL CHART: TOP to BOTTOM | ALL UNITS ARE IN MILS | PLATED | NON-PLATED | QTY | 301 | 229 | 12 | 98 | 8 | 2 | 3 | Model | SV7220G2 PCIE RISER | PCB_NO | 13523 | VER. | 1B | Layer | L1 | L2GND | L3 | TPLACE | Designer | IVY | Date | 02/05/2013 | BPLACE | L4VCC | L5GND | L6
